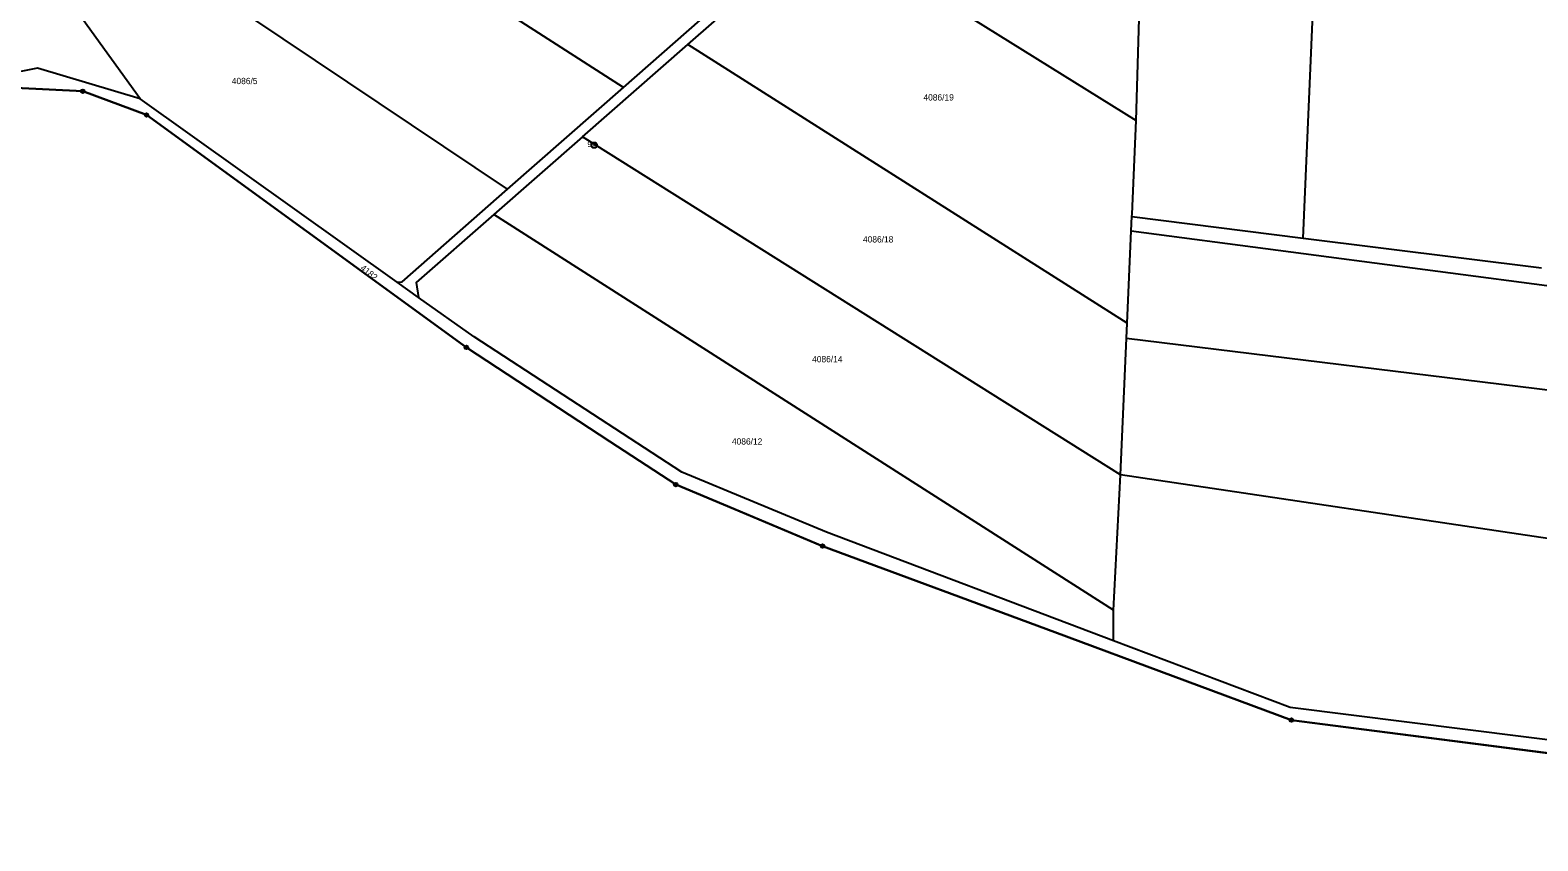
# Model space of a CAD drawing. Extents: x -733394 to -722299, y -1082822 to -1075049.
# Drawn here: x -729569.1 to -729161.7, y -1082224.1 to -1082004.9 of the extents above; entities that cross this region are included whole.
import ezdxf

# ---------------------------------------------------------------- set-up
doc = ezdxf.new("R2010")
doc.units = 0
for name, color, linetype in [('Hranice parcel', 7, 'Continuous'), ('Parcelní čísla', 7, 'Continuous'), ('Polygon ku', 7, 'Continuous'), ('Značky bodu BP', 7, 'Continuous')]:
    doc.layers.add(name, color=color, linetype=linetype)

msp = doc.modelspace()

# ---------------------------------------------------------------- linework, layer by layer
at = {"layer": 'Hranice parcel'}
for p, q in [((-729270.18, -1082029.29), (-729266.63, -1081899.59)), ((-729408.79, -1082020.42), (-729522.58, -1081947.15)), ((-729440.11, -1082047.92), (-729555.32, -1081970.56)), ((-729391.36, -1082008.8), (-729354.74, -1081976.73)), ((-729354.74, -1081976.73), (-729270.18, -1082029.29)), ((-729408.79, -1082020.42), (-729384.33, -1081998.94)), ((-729419.84, -1082033.74), (-729391.36, -1082008.8)), ((-729272.64, -1082084.11), (-729391.36, -1082008.8)), ((-729440.11, -1082047.92), (-729408.79, -1082020.42)), ((-729469.88, -1082073.07), (-729539.42, -1082023.51)), ((-729451.21, -1082090.67), (-729537.64, -1082027.84)), ((-729419.84, -1082033.74), (-729443.8, -1082054.71)), ((-729274.48, -1082125.16), (-729419.84, -1082033.74)), ((-729276.29, -1082161.69), (-729443.8, -1082054.71)), ((-729271.52, -1082059.2), (-729271.35, -1082055.3)), ((-729271.35, -1082055.3), (-729225.08, -1082061.1)), ((-729272.64, -1082084.11), (-729271.52, -1082059.2)), ((-729271.52, -1082059.2), (-728959.82, -1082100.04)), ((-729225.08, -1082061.1), (-729160.63, -1082069.18)), ((-729464.15, -1082077.15), (-729469.88, -1082073.07)), ((-729272.82, -1082088.22), (-729272.64, -1082084.11)), ((-729274.48, -1082125.16), (-729272.82, -1082088.22)), ((-729272.82, -1082088.22), (-728962.27, -1082126.11)), ((-729412.44, -1082116.1), (-729451.21, -1082090.67)), ((-729394.65, -1082127.77), (-729412.44, -1082116.1)), ((-729276.29, -1082161.69), (-729274.48, -1082125.16)), ((-728968.56, -1082170.78), (-729274.48, -1082125.16)), ((-729378.95, -1082134.34), (-729394.65, -1082127.77)), ((-729354.94, -1082144.4), (-729378.95, -1082134.34)), ((-729292.17, -1082167.69), (-729354.94, -1082144.4)), ((-729276.3, -1082169.99), (-729276.29, -1082161.69)), ((-729228.26, -1082191.41), (-729292.17, -1082167.69)), ((-729219.84, -1082192.5), (-729228.26, -1082191.41)), ((-728975.07, -1082224.07), (-729219.84, -1082192.5))]:
    msp.add_line(p, q, dxfattribs=at)
for points in [[(-729225.08, -1082061.1), (-729213.41, -1081791.58), (-729209.9, -1081685.66)], [(-729539.42, -1082023.51), (-729562.6, -1081991.22), (-729566, -1081978.2)], [(-729539.42, -1082023.51), (-729567.15, -1082015.22), (-729608.63, -1082023.39)], [(-729537.64, -1082027.84), (-729554.88, -1082021.41), (-729573.07, -1082020.5)], [(-729271.35, -1082055.3), (-729271.32, -1082054.68), (-729270.18, -1082029.29)], [(-729469.88, -1082073.07), (-729468.59, -1082072.93), (-729440.11, -1082047.92)], [(-729443.8, -1082054.71), (-729464.79, -1082073.09), (-729464.15, -1082077.15)], [(-729276.3, -1082169.99), (-729353.9, -1082140.62), (-729393.02, -1082124.4), (-729449.15, -1082087.84), (-729464.15, -1082077.15)], [(-728974.19, -1082219.99), (-729228.58, -1082188.05), (-729276.3, -1082169.99)]]:
    msp.add_lwpolyline(points, dxfattribs=at)
at = {"layer": 'Polygon ku'}
msp.add_lwpolyline([(-729573.07, -1082020.5), (-729554.88, -1082021.41), (-729537.64, -1082027.84), (-729451.21, -1082090.67), (-729412.44, -1082116.1), (-729394.65, -1082127.77), (-729378.95, -1082134.34), (-729354.94, -1082144.4), (-729292.17, -1082167.69), (-729228.26, -1082191.41), (-729219.84, -1082192.5), (-728975.07, -1082224.07)], dxfattribs=at)
at = {"layer": 'Značky bodu BP'}
for centre, radius in [((-729554.88, -1082021.41), 0.5), ((-729554.88, -1082021.41), 0.0303), ((-729537.64, -1082027.84), 0.5), ((-729537.64, -1082027.84), 0.0303), ((-729416.7, -1082036), 0.75), ((-729416.7, -1082036), 0.03), ((-729451.21, -1082090.67), 0.5), ((-729451.21, -1082090.67), 0.0303), ((-729394.65, -1082127.77), 0.5), ((-729394.65, -1082127.77), 0.0303), ((-729354.94, -1082144.4), 0.5), ((-729354.94, -1082144.4), 0.0303), ((-729228.26, -1082191.41), 0.5), ((-729228.26, -1082191.41), 0.0303)]:
    msp.add_circle(centre, radius, dxfattribs=at)

# ---------------------------------------------------------------- texts
at = {"layer": 'Parcelní čísla'}
for s, p in [('4086/5', (-729514.62, -1082019.5)), ('4086/19', (-729327.7, -1082023.93)), ('4086/18', (-729344.04, -1082062.31)), ('4086/14', (-729357.78, -1082094.7)), ('4086/12', (-729379.45, -1082116.94))]:
    msp.add_text(s, height=1.7, dxfattribs=at).set_placement(p)
msp.add_text('4182', height=1.7, rotation=321, dxfattribs=at).set_placement((-729480.03, -1082069.5))
at = {"layer": 'Značky bodu BP'}
msp.add_text('9', height=1.5, dxfattribs=at).set_placement((-729418.51, -1082036.5))

doc.saveas('drawing.dxf')
